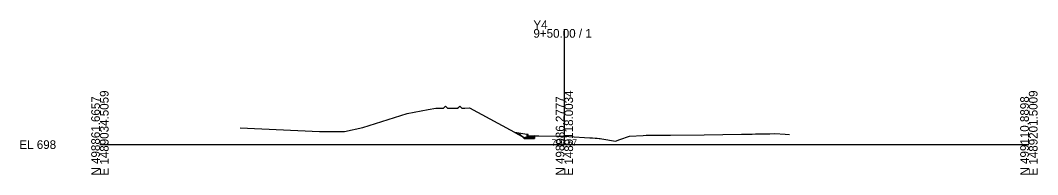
# Model space of a CAD drawing. Extents: x -26 to 1489054, y -10 to 499098.
# Drawn here: x 2774.3 to 3102.8, y 490.3 to 540.1 of the extents above; entities that cross this region are included whole.
import ezdxf

# ---------------------------------------------------------------- set-up
doc = ezdxf.new("R2010")
doc.units = 0
for name, color, linetype in [('Exist Cross Section Cell', 7, 'Continuous'), ('Exist XS Center Line Elevation Label', 7, 'Continuous'), ('Exist XS Ground Line', 7, 'Continuous'), ('Prop CMT Conc Surface', 7, 'Continuous'), ('Prop CMT Concrete Structures', 7, 'Continuous'), ('Prop CMT Pvmt Course 1 CG', 7, 'Continuous'), ('Prop CMT Slope Grass', 7, 'Continuous'), ('Prop CMT Subgrade Earthwork', 7, 'Continuous'), ('Prop XS Earthwork Shape', 7, 'Continuous'), ('Scratch_Level_1', 7, 'Continuous')]:
    doc.layers.add(name, color=color, linetype=linetype)

msp = doc.modelspace()

# ---------------------------------------------------------------- linework, layer by layer
at = {"layer": 'Exist Cross Section Cell'}
for p, q in [((2950, 500), (2950, 537.31)), ((2800, 500), (2950, 500)), ((2950, 500), (3100, 500))]:
    msp.add_line(p, q, dxfattribs=at)
at = {"layer": 'Exist XS Ground Line'}
msp.add_lwpolyline([(2845.35, 505.47), (2870.95, 504.26), (2878.96, 504.25), (2884.94, 505.52), (2899.22, 510.01), (2906.06, 511.32), (2908.46, 511.76), (2909.69, 511.77), (2911, 511.77), (2911.6, 512.43), (2912.24, 511.78), (2914.07, 511.79), (2915.49, 511.79), (2915.89, 512.09), (2916.27, 512.44), (2916.6, 512.1), (2916.9, 511.8), (2917.83, 511.81), (2919.34, 511.82), (2932.5, 504.73), (2937.09, 502.27), (2938.22, 502.5), (2939.04, 502.67), (2939.6, 502.73), (2940.33, 502.84), (2941.09, 502.87), (2941.79, 502.85), (2948.3, 502.71), (2949.78, 502.69), (2951.46, 502.59), (2958.2, 502.22), (2959.11, 502.17), (2959.92, 502.12), (2960.57, 502.06), (2961.25, 502), (2961.58, 501.97), (2962.09, 501.88), (2966.49, 501.14), (2967.93, 501.7), (2970.99, 502.75), (2975.39, 502.93), (2976.39, 503.01), (2977.09, 503.02), (2981.24, 503.1), (2984.3, 503.09), (2995.18, 503.19), (3007.17, 503.38), (3010.62, 503.4), (3011.72, 503.44), (3012.52, 503.44), (3014.27, 503.43), (3014.88, 503.43), (3016.35, 503.43), (3017.98, 503.55), (3021.26, 503.38), (3022.74, 503.26)], dxfattribs=at)
at = {"layer": 'Prop CMT Conc Surface'}
for points in [[(2938.33, 502.78), (2938.33, 503.28), (2937.83, 503.28)], [(2940.33, 502.84), (2938.33, 502.78)]]:
    msp.add_lwpolyline(points, dxfattribs=at)
at = {"layer": 'Prop CMT Concrete Structures'}
for points in [[(2940.33, 502.84), (2938.33, 502.78), (2938.33, 503.28), (2937.83, 503.28)], [(2937.83, 503.28), (2937.83, 502.28), (2940.33, 502.26)], [(2940.33, 502.26), (2940.33, 502.84)]]:
    msp.add_lwpolyline(points, dxfattribs=at)
at = {"layer": 'Prop CMT Pvmt Course 1 CG'}
for points in [[(2940.33, 502.26), (2937.33, 502.28), (2937.04, 501.99)], [(2937.04, 501.99), (2940.33, 501.97)], [(2940.33, 501.97), (2940.33, 502.26)]]:
    msp.add_lwpolyline(points, dxfattribs=at)
at = {"layer": 'Prop CMT Slope Grass'}
msp.add_line((2937.83, 503.28), (2934.04, 503.91), dxfattribs=at)
at = {"layer": 'Prop CMT Subgrade Earthwork'}
msp.add_line((2940.33, 501.97), (2940.33, 502.84), dxfattribs=at)
msp.add_lwpolyline([(2940.33, 501.97), (2937.04, 501.99), (2935.34, 503.69)], dxfattribs=at)
at = {"layer": 'Prop XS Earthwork Shape'}
for points in [[(2936.39, 502.64), (2935.34, 503.69), (2934.04, 503.91)], [(2940.33, 501.97), (2937.04, 501.99), (2936.39, 502.64), (2937.09, 502.27), (2938.22, 502.5), (2939.04, 502.67), (2939.6, 502.73), (2940.33, 502.84)]]:
    msp.add_lwpolyline(points, close=True, dxfattribs=at)

# ---------------------------------------------------------------- texts
at = {"layer": 'Exist Cross Section Cell'}
for s, p in [('Y4', (2940, 537.31)), ('9+50.00 / 1', (2940, 534.51)), ('EL 698', (2774, 498.6))]:
    msp.add_text(s, height=2.8, dxfattribs=at).set_placement(p)
for s, p in [('E 1489034.5059', (2802.8, 490)), ('E 1489118.0034', (2952.8, 490)), ('E 1489201.5009', (3102.8, 490)), ('N 498861.6657', (2800, 490)), ('N 498986.2777', (2950, 490)), ('N 499110.8898', (3100, 490))]:
    msp.add_text(s, height=2.8, rotation=90, dxfattribs=at).set_placement(p)
at = {"layer": 'Exist XS Center Line Elevation Label'}
msp.add_text('700.67', height=2, dxfattribs=at).set_placement((2945.87, 499.67))
at = {"layer": 'Scratch_Level_1'}
for s, p in [('LT_CG_Top_BOC', (2937.72, 503.27)), ('LT_CG_Top_Face', (2938.21, 503.27)), ('LT_CG_Top_Gut', (2938.22, 502.77)), ('LT_Sub_OEOP', (2936.95, 501.98)), ('LT_CG1_Shelf_Out', (2937.2, 502.27)), ('LT_CG_Bot_BOC', (2937.72, 502.27))]:
    msp.add_text(s, height=0.02, dxfattribs=at).set_placement(p)

doc.saveas('drawing.dxf')
